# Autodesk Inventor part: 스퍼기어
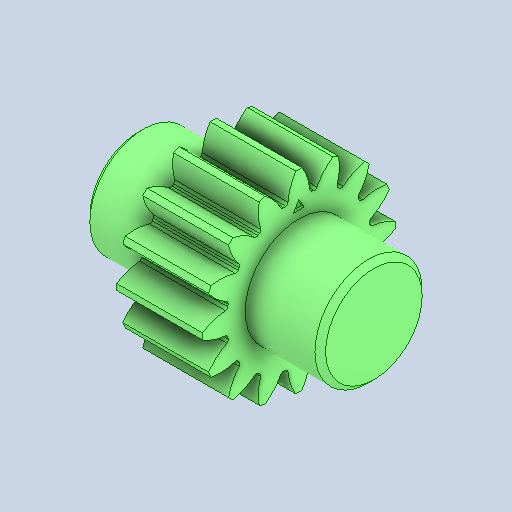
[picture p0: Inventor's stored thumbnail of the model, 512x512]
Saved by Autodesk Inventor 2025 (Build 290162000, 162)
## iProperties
Created: 2026-08
Part Number: 스퍼기어
Material: 강철, 합금
Document SubType Name: Modeling
Designer: KDI
Density: 7.73 g/cm^3
Appearance: 기본값
Author: jhkim
Sending System: Autodesk Inventor 2027
Preprocessor: ST-DEVELOPER v20.1
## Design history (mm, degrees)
feature "솔리드1"
node "솔리드2"
